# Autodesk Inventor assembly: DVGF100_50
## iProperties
Created: 2010-04
Part Number: DVGF100_50
Document SubType Name: Assembly
Designer: TB
Mass: 3151.55 g
Surface Area: 3270.78 cm^2
Volume: 3151.55 cm^3
Density: 1 g/cm^3
Description: KM DVGF 100/50 - 100 mm
Slaglengde: 100.000 mm
Author: TB
